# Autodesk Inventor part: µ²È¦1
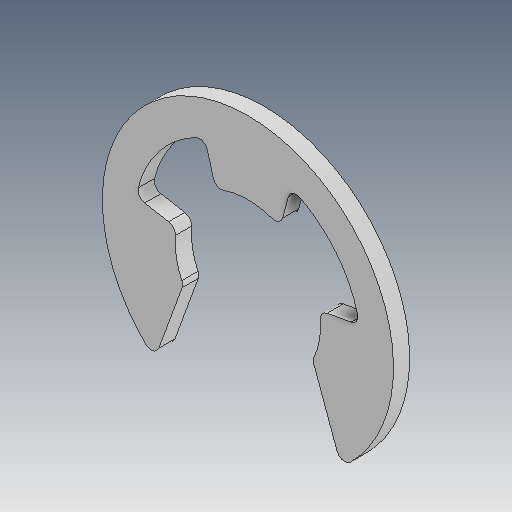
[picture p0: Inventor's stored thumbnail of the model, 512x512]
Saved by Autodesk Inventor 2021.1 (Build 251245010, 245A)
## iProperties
Created: 2014-12
Part Number: µ²È¦1
Material: Ogólny
Document SubType Name: Modeling
Designer: user
Density: 1 g/cm^3
Appearance: Domyślna
Author: user
Revision Number: ÈÎºÎ
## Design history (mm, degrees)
feature "ÊäÈë1"
node "Bryła1"
